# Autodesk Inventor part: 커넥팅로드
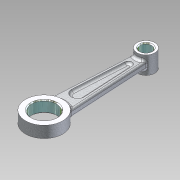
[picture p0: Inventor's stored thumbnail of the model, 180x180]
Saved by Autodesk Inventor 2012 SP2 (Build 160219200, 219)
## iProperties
Manager: KYOUNG IL JANG
Company: 한국ATC센터
Created: 2012-10
Part Number: 커넥팅로드
Document SubType Name: Modeling
Density: 1 g/cm^3
Checked By: KYOUNG IL JANG
Vendor: CBT Solutions
Designer: KYOUNG IL JANG
Material: 기본값
Author: KYOUNG IL JANG
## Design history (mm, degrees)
sketch "스케치1"
  geometry: L1 (-19.879, 82.758)-(-19.879, 197.758); L2 (-27.379, 191.144)-(-32.379, 99.633); L3 (-12.379, 191.144)-(-7.379, 99.633); C1 r 14 at (-19.879, 82.758); C2 r 6.5 at (-19.879, 197.758); A1 r 19 centre (-19.879, 82.758) between (-20.11, 101.757) and (-19.649, 63.76) reference; A2 r 21 centre (-19.879, 82.758) between (-32.379, 99.633) and (-7.379, 99.633); A3 r 10 centre (-19.879, 197.758) between (-27.379, 191.144) and (-12.379, 191.144); 1 further point
  constraints: 6 end point, 4 centre point, 4 coincident, 4 point on circle, 2 horizontal alignment, 1 equal length, 1 vertical
  dimensions: "d0" = 28 diameter of C1; "d1" = 42 diameter of A2; "d4" = 115 distance of L1.end C1.centre; "d5" = 20 diameter of A3; "d6" = 13 diameter of C2; "d7" = 25 distance of L3.end L2.end; "d8" = 15 distance of L3.start L2.start
  node "참조1"
extrude "돌출1" new body sketch "스케치1" stored distance "d2" = 13; taper "d3" = 0 deg
extrude "돌출2" join sketch "스케치1" stored distance "d9" = 20; taper "d10" = 0 deg
extrude "돌출3" join sketch "스케치1" stored distance "d11" = 8; taper "d12" = 0 deg
sketch "스케치2"
  geometry: L1 (7.379, 99.633)-(12.379, 191.144) reference; L2 (27.379, 191.144)-(32.379, 99.633) reference; L3 (27.197, 121.158)-(24.092, 177.989); L4 (15.667, 177.989)-(12.561, 121.158); A1 r 21 centre (19.879, 82.758) between (7.379, 99.633) and (32.379, 99.633) reference; A2 r 7.329 centre (19.879, 120.758) between (12.561, 121.158) and (27.197, 121.158); A3 r 4.219 centre (19.879, 177.758) between (24.092, 177.989) and (15.667, 177.989); A4 r 10 centre (19.879, 197.758) between (12.379, 191.144) and (27.379, 191.144) reference; 2 further points
  constraints: 4 end point, 4 point on circle, 4 tangent, 2 centre point, 2 parallel, 1 coincident, 3 other
  dimensions: "d16" = 38 distance of A2.centre A1.centre; "d17" = 4 distance between parallel lines of L2 L3; "d18" = 4 distance between parallel lines of L4 L1; "d25" = 20 distance of A3.centre A4.centre
extrude "돌출4" cut sketch "스케치2" distance "d19" = 5; taper "d20" = 0 deg
fillet "모깎기1" dims "d21" = 2
fillet "모깎기2" dims "d22" = 3
fillet "모깎기3" dims "d23" = 3
chamfer "모따기1" distance "d26" = 1; stored, may be unused: second distance "d27" = 2, angle "d28" = 45 deg
chamfer "모따기2" distance "d29" = 1; stored, may be unused: second distance "d30" = 2, angle "d31" = 45 deg
node "솔리드1"
mirror "대칭1"
other parameters: "d13" = 5, "d14" = 5
